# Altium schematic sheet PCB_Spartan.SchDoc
size A4
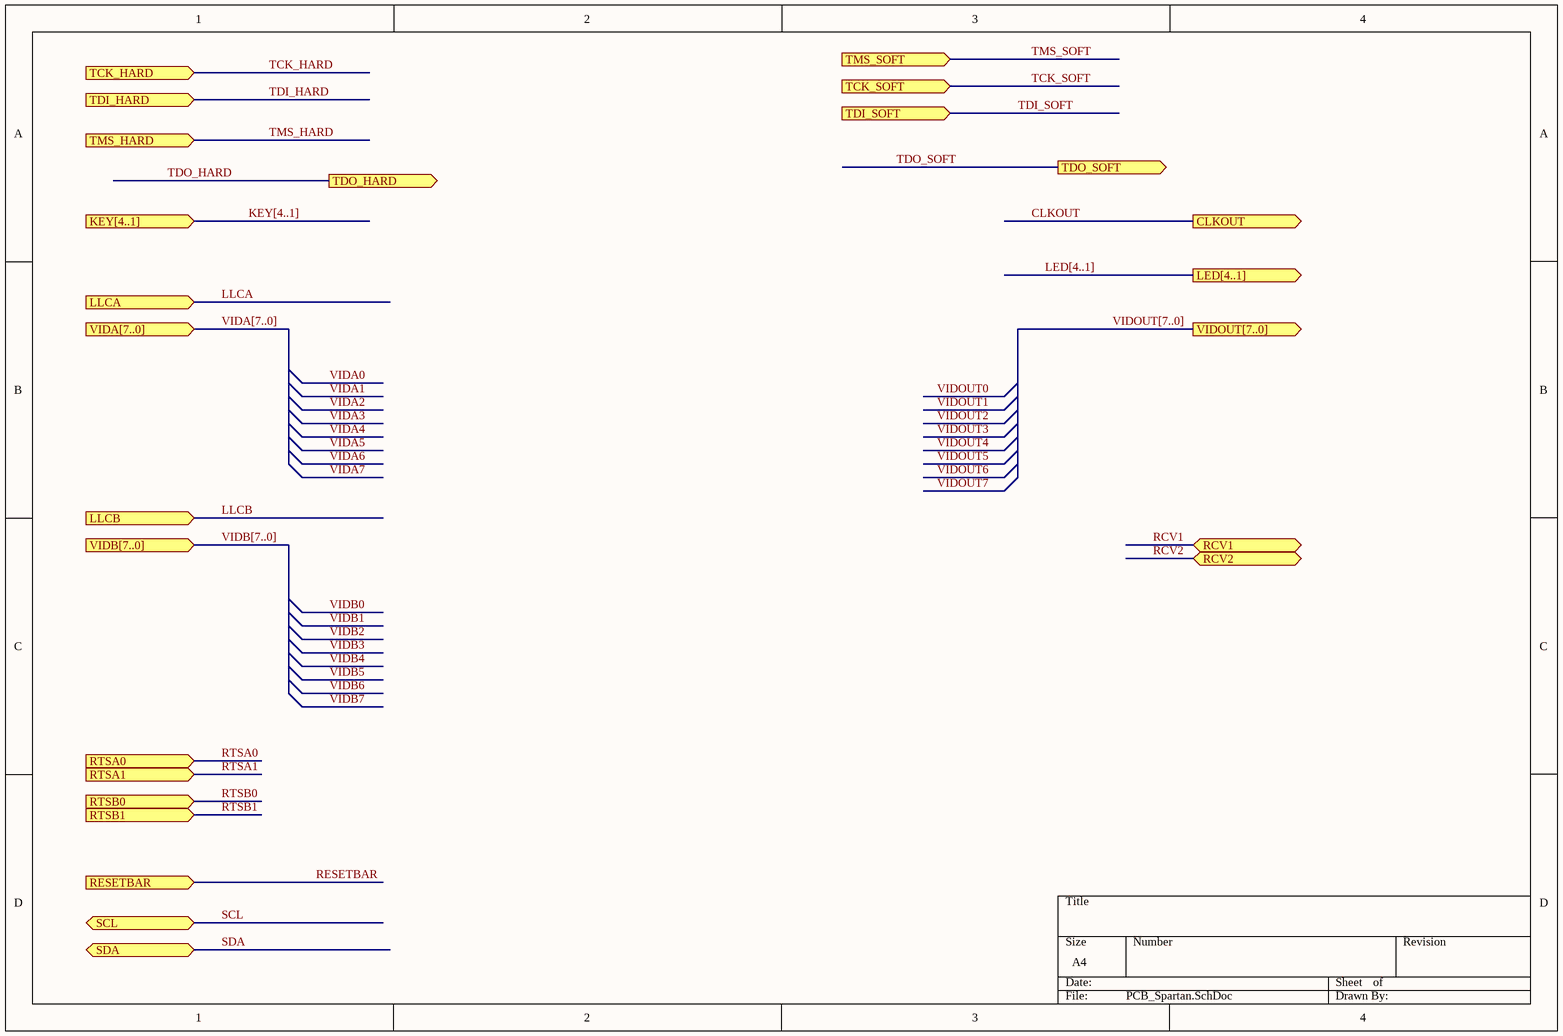
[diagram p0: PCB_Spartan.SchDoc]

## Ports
CLKOUT (out), KEY[4..1] (in), LED[4..1] (out), LLCA (in), LLCB (in), RCV1 (bidir), RCV2 (bidir), RESETBAR (in), RTSA0 (in), RTSA1 (in), RTSB0 (in), RTSB1 (in), SCL (bidir), SDA (bidir), TCK_HARD (in), TCK_SOFT (in), TDI_HARD (in), TDI_SOFT (in), TDO_HARD (out), TDO_SOFT (out), TMS_HARD (in), TMS_SOFT (in), VIDA[7..0] (in), VIDB[7..0] (in), VIDOUT[7..0] (out)

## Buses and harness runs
bus KEY[4..1] = port KEY[4..1]
bus LED[4..1] = port LED[4..1]
bus VIDA[7..0] = port VIDA[7..0]
bus VIDB[7..0] = port VIDB[7..0]
bus VIDOUT[7..0] = port VIDOUT[7..0]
